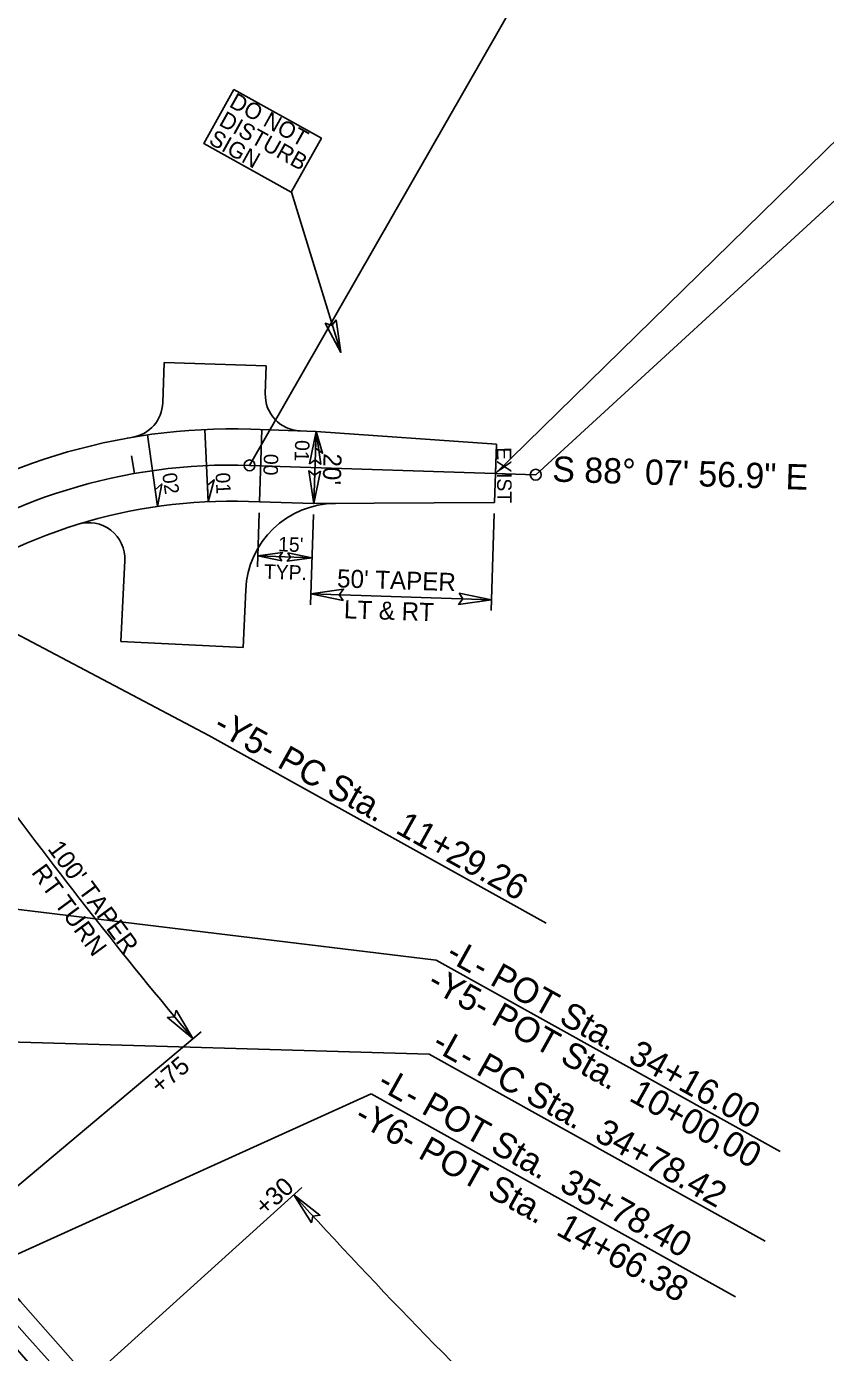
# Model space of a CAD drawing. Extents: x 1762196 to 1766326, y 709922 to 713142.
# Drawn here: x 1764189.7 to 1764410.7, y 711303.2 to 711670.2 of the extents above; entities that cross this region are included whole.
import ezdxf

# ---------------------------------------------------------------- set-up
doc = ezdxf.new("R2010")
doc.units = 0
for name, color, linetype in [('Old_Level_3', 7, 'Continuous'), ('Pattern 1', 7, 'Continuous'), ('Pattern 2', 7, 'Continuous'), ('Prop Conc 2ft 6in Curb and Gutter', 7, 'Continuous'), ('Prop Dimension', 7, 'Continuous'), ('Prop EOT', 7, 'Continuous'), ('Prop Horizontal Alignment', 7, 'Continuous'), ('Prop Horizontal Alignment Direction Label', 7, 'Continuous'), ('Prop Horizontal Alignment Station Label', 7, 'Continuous'), ('Prop Horizontal Alignment Tick Small', 7, 'Continuous'), ('Prop Lane Lines', 7, 'Continuous'), ('Prop Superelevation  Arrow CELL', 7, 'Continuous'), ('Prop Superelevation Label', 7, 'Continuous'), ('Prop Terminator CELL', 7, 'Continuous')]:
    doc.layers.add(name, color=color, linetype=linetype)

msp = doc.modelspace()

# ---------------------------------------------------------------- linework, layer by layer
at = {"layer": 'Old_Level_3'}
for p, q in [((1764227.71, 711577.22), (1764227.35, 711566.04)), ((1764255.98, 711576.3), (1764227.71, 711577.22)), ((1764255.98, 711576.3), (1764255.73, 711568.58)), ((1764216.89, 711522.38), (1764215.81, 711499.98)), ((1764249.62, 711498.34), (1764250.31, 711514.24)), ((1764249.62, 711498.34), (1764215.81, 711499.98))]:
    msp.add_line(p, q, dxfattribs=at)
for centre, radius, start, end in [((1764217.35, 711566.36), 10, 279.593, 358.1325), ((1764265.72, 711568.26), 10, 178.1325, 268.1325), ((1764275.28, 711513.17), 25, 90.3268, 177.5291), ((1764206.91, 711522.86), 10, 357.231, 107.1185)]:
    msp.add_arc(centre, radius, start, end, dxfattribs=at)
at = {"layer": 'Pattern 1'}
for radius in [1468.5, 1473.5]:
    msp.add_arc((1765296.46, 712280.56), radius, 220.01407, 240.8436, dxfattribs=at)
at = {"layer": 'Pattern 2'}
for radius in [1468.5, 1473.5]:
    msp.add_arc((1765296.46, 712280.56), radius, 220.01407, 240.8436, dxfattribs=at)
at = {"layer": 'Prop Conc 2ft 6in Curb and Gutter'}
msp.add_arc((1765296.46, 712280.56), 1478, 220.01407, 240.8436, dxfattribs=at)
at = {"layer": 'Prop Dimension'}
for p, q in [((1764262.94, 711624.32), (1764276.66, 711579.96)), ((1764269.12, 711538.13), (1764269.77, 711558.12)), ((1764268.2, 711510.15), (1764269.02, 711535.13)), ((1764318.18, 711508.52), (1764319.05, 711535.42)), ((1764268.3, 711513.14), (1764318.28, 711511.51)), ((1764238.01, 711391.97), (1764166.78, 711332.17)), ((1764265.83, 711348.82), (1764202.31, 711291.39))]:
    msp.add_line(p, q, dxfattribs=at)
msp.add_lwpolyline([(1764247.02, 711652.72), (1764271.24, 711639.23), (1764262.93, 711624.31), (1764238.71, 711637.8)], close=True, dxfattribs=at)
for radius, start, end in [(1385, 216.32502, 220.01407), (1392.37, 222.11492, 230.90027)]:
    msp.add_arc((1765296.46, 712280.56), radius, start, end, dxfattribs=at)
at = {"layer": 'Prop EOT'}
for p, q in [((1764251.69, 711558.71), (1764269.77, 711558.12)), ((1764269.77, 711558.12), (1764319.68, 711554.54)), ((1764319.68, 711554.54), (1764319.15, 711538.42)), ((1764251.04, 711538.72), (1764269.12, 711538.13)), ((1764269.12, 711538.13), (1764319.15, 711538.42))]:
    msp.add_line(p, q, dxfattribs=at)
for centre, radius, start, end in [((1764246.35, 711394.8), 164, 88.1325, 126.325), ((1764246.35, 711394.8), 144, 88.1325, 126.325), ((1765296.46, 712280.56), 1480, 220.01407, 240.8436)]:
    msp.add_arc(centre, radius, start, end, dxfattribs=at)
at = {"layer": 'Prop Horizontal Alignment'}
msp.add_line((1764251.37, 711548.71), (1764330.54, 711546.13), dxfattribs=at)
for centre, radius, start, end in [((1764246.35, 711394.8), 154, 88.1325, 126.325), ((1765296.46, 712280.56), 1500, 216.32502, 240.8436)]:
    msp.add_arc(centre, radius, start, end, dxfattribs=at)
at = {"layer": 'Prop Horizontal Alignment Station Label'}
for p, q in [((1764251.37, 711548.71), (1764364.45, 711746.43)), ((1764461.21, 711685.37), (1764319.42, 711546.5)), ((1764330.54, 711546.13), (1764451.2, 711656.86)), ((1764155.12, 711518.87), (1764240.1, 711473.99)), ((1764333.42, 711422.02), (1764240.1, 711473.99)), ((1764050.98, 711442.3), (1764302.99, 711411.76)), ((1764398.13, 711358.78), (1764302.99, 711411.76)), ((1764087.96, 711392.01), (1764301.04, 711385.77)), ((1764394.04, 711333.98), (1764301.04, 711385.77)), ((1764149.82, 711313.49), (1764285.02, 711374.75)), ((1764385.85, 711318.61), (1764285.02, 711374.75))]:
    msp.add_line(p, q, dxfattribs=at)
for centre in [(1764251.37, 711548.71), (1764330.54, 711546.13)]:
    msp.add_circle(centre, 1.5, dxfattribs=at)
at = {"layer": 'Prop Horizontal Alignment Tick Small'}
for p, q in [((1764219.59, 711546.45), (1764218.72, 711551.38)), ((1764319.42, 711546.5), (1764319.58, 711551.49))]:
    msp.add_line(p, q, dxfattribs=at)
at = {"layer": 'Prop Lane Lines'}
msp.add_arc((1765296.46, 712280.56), 1520, 216.32502, 224.72992, dxfattribs=at)
at = {"layer": 'Prop Superelevation  Arrow CELL'}
for points in [[(1764269.77, 711558.12), (1764271.57, 711552.06), (1764269.62, 711553.5)], [(1764239.9, 711538.65), (1764241.63, 711544.74), (1764239.7, 711543.27)], [(1764225.94, 711537.34), (1764227.07, 711543.57), (1764225.29, 711541.92)]]:
    msp.add_lwpolyline(points, close=True, dxfattribs=at)
at = {"layer": 'Prop Superelevation Label'}
for p, q in [((1764239.01, 711558.63), (1764239.9, 711538.65)), ((1764254.78, 711558.61), (1764254.12, 711538.62)), ((1764223.11, 711557.14), (1764225.94, 711537.34)), ((1764269.77, 711558.12), (1764269.12, 711538.13)), ((1764254.03, 711535.62), (1764253.54, 711520.63)), ((1764253.64, 711523.63), (1764268.63, 711523.14))]:
    msp.add_line(p, q, dxfattribs=at)
at = {"layer": 'Prop Terminator CELL'}
for points in [[(1764275.31, 711588.99), (1764276.66, 711579.96), (1764272.3, 711588.05), (1764274.18, 711587.46)], [(1764267.93, 711549.18), (1764269.77, 711558.12), (1764271.07, 711549.02), (1764269.51, 711550.22)], [(1764270.96, 711547.08), (1764269.12, 711538.13), (1764267.81, 711547.23), (1764269.37, 711546.03)], [(1764260.34, 711522.25), (1764253.64, 711523.63), (1764260.46, 711524.61), (1764259.56, 711523.43)], [(1764261.92, 711524.52), (1764268.63, 711523.14), (1764261.8, 711522.16), (1764262.71, 711523.33)], [(1764277.25, 711511.3), (1764268.3, 711513.14), (1764277.4, 711514.45), (1764276.2, 711512.89)], [(1764309.33, 711513.36), (1764318.28, 711511.51), (1764309.18, 711510.21), (1764310.38, 711511.77)], [(1764231.11, 711397.93), (1764235.71, 711390.04), (1764228.67, 711395.94), (1764230.63, 711396.09)], [(1764268.49, 711339.09), (1764263.6, 711346.81), (1764270.86, 711341.17), (1764268.9, 711340.95)]]:
    msp.add_lwpolyline(points, close=True, dxfattribs=at)

# ---------------------------------------------------------------- texts
at = {"layer": 'Prop Dimension'}
for s, height, rotation, p in [('DO NOT ', 4.5, 330.8875, (1764245.48, 711648.12)), ('DISTURB', 4.5, 330.8875, (1764242.63, 711643.01)), ('SIGN', 4.5, 330.8875, (1764239.79, 711637.9)), ("20'", 5, 268.1325, (1764271.88, 711552.1)), ('EXIST', 4, 270.4766, (1764319.78, 711553.71)), ("50' TAPER", 5, 358.1325, (1764275.52, 711514.96)), ('LT & RT', 5, 358.1325, (1764277.42, 711506.39)), ("100' TAPER", 5, 306.325, (1764195.31, 711442.58)), ('RT TURN', 5, 306.325, (1764190.82, 711436.02)), ('+75', 5, 40.0141, (1764226.55, 711374.46)), ('+30', 5, 42.1149, (1764255.63, 711340.81))]:
    msp.add_text(s, height=height, rotation=rotation, dxfattribs=at).set_placement(p)
at = {"layer": 'Prop Horizontal Alignment Direction Label'}
msp.add_text('S 88%%d 07\' 56.9" E', height=7, rotation=358.1325, dxfattribs=at).set_placement((1764335.06, 711544.25))
at = {"layer": 'Prop Horizontal Alignment Station Label'}
for s, p in [('-Y5- PC Sta.  11+29.26', (1764240.98, 711475.25)), ('-L- POT Sta.  34+16.00', (1764305.28, 711412)), ('-Y5- POT Sta.  10+00.00', (1764300.14, 711404.17)), ('-L- PC Sta.  34+78.42', (1764301.44, 711387.21)), ('-L- POT Sta.  35+78.40', (1764286.31, 711376.38)), ('-Y6- POT Sta.  14+66.38', (1764279.96, 711367.1))]:
    msp.add_text(s, height=7, rotation=330.8875, dxfattribs=at).set_placement(p)
at = {"layer": 'Prop Superelevation Label'}
for s, rotation, p in [('01', 268.1325, (1764264, 711555.78)), ('00', 268.1325, (1764255.37, 711551.95)), ('02', 278.1461, (1764227.19, 711546.37)), ('01', 272.5653, (1764241.97, 711546.63)), ("15'", 358.1325, (1764259.23, 711524.93)), ('TYP.', 358.1325, (1764255.3, 711517.36))]:
    msp.add_text(s, height=4, rotation=rotation, dxfattribs=at).set_placement(p)

doc.saveas('drawing.dxf')
